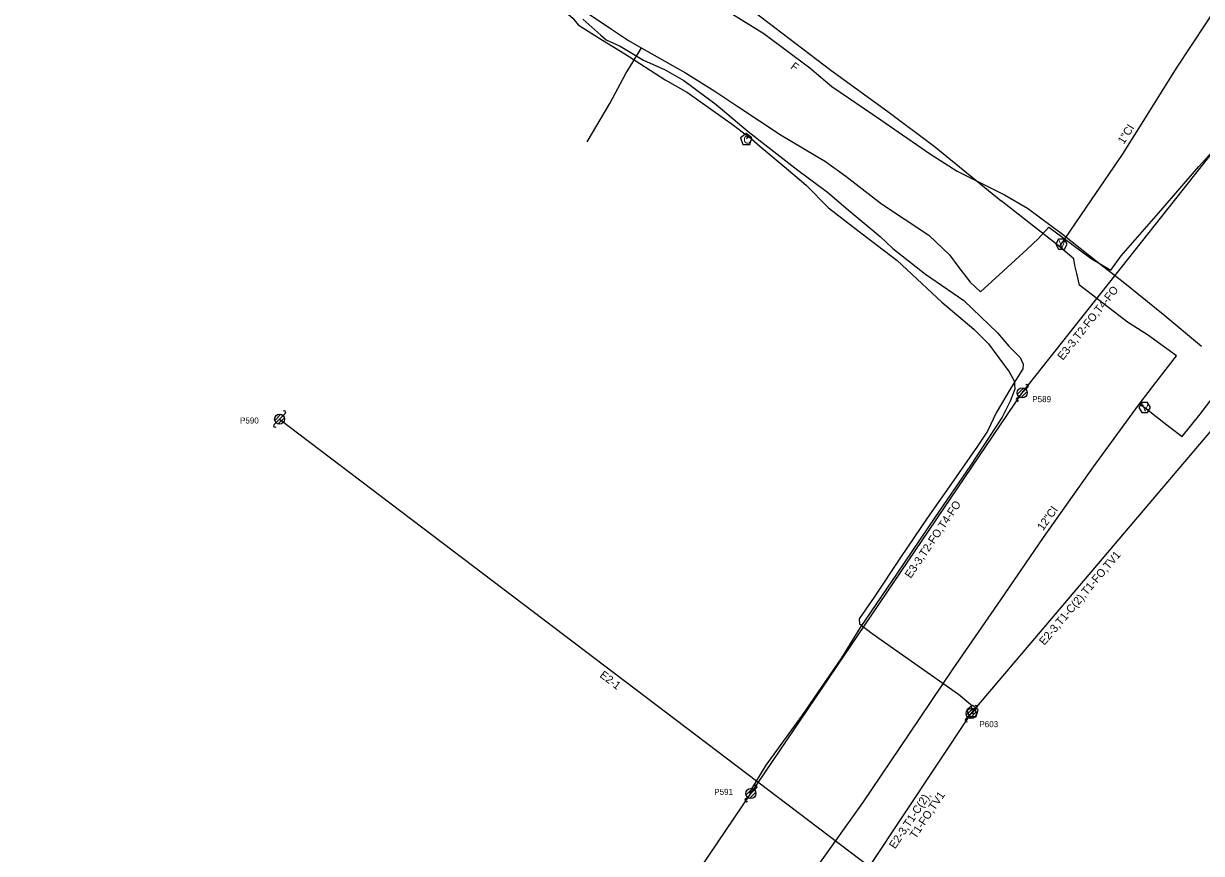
# Model space of a CAD drawing. Extents: x 1614474 to 1865144, y 1098877 to 1212550.
# Drawn here: x 1811697 to 1812286, y 1188970 to 1189385 of the extents above; entities that cross this region are included whole.
import ezdxf

# ---------------------------------------------------------------- set-up
doc = ezdxf.new("R2010")
doc.units = 0
for name, color, linetype in [('RD_EX_SU_Gas', 7, 'Continuous'), ('RD_EX_SU_H2O', 7, 'Continuous'), ('RD_EX_SU_Ovhd', 7, 'Continuous'), ('RD_EX_SU_Pole', 7, 'Continuous'), ('RD_EX_SU_Telecom', 7, 'Continuous'), ('RD_EX_SU_TX_H2O', 7, 'Continuous'), ('RD_EX_SU_TX_Pole', 7, 'Continuous'), ('RD_EX_SU_TX_Telecom', 7, 'Continuous')]:
    doc.layers.add(name, color=color, linetype=linetype)

# ---------------------------------------------------------------- blocks, each defined once
blk = doc.blocks.new('SUE_PP')
at = {"layer": 'RD_EX_SU_Pole'}
for p, q in [((-2.41, -0.65), (0.65, 2.41)), ((-1.77, -1.77), (1.77, 1.77)), ((-0.65, -2.41), (2.41, 0.65)), ((1.77, 1.77), (2.83, 2.83)), ((-2.83, -2.83), (-1.77, -1.77))]:
    blk.add_line(p, q, dxfattribs=at)
blk.add_circle((0, 0), 2.5, dxfattribs=at)
for centre, start, end in [((2.3, 3.36), 315, 135), ((-2.3, -3.36), 135, 315)]:
    blk.add_arc(centre, 0.75, start, end, dxfattribs=at)
blk = doc.blocks.new('SUE_WV')
at = {"layer": 'RD_EX_SU_H2O'}
blk.add_lwpolyline([(2.89, 0), (1.44, 2.5), (-1.44, 2.5), (-2.89, 0), (-1.44, -2.5), (1.44, -2.5)], close=True, dxfattribs=at)
blk.add_text('V', height=3.75, dxfattribs=at).set_placement((-1.43, -1.88))
blk = doc.blocks.new('SUE_TVP')
at = {"layer": 'RD_EX_SU_Telecom'}
blk.add_lwpolyline([(0, 3), (-2.85, 0.93), (-1.76, -2.43), (1.76, -2.43), (2.85, 0.93)], close=True, dxfattribs=at)
blk.add_text('C', height=4, dxfattribs=at).set_placement((-1.43, -2))
blk = doc.blocks.new('SUE_TPP')
at = {"layer": 'RD_EX_SU_Telecom'}
blk.add_lwpolyline([(0, 3), (-2.85, 0.93), (-1.76, -2.43), (1.76, -2.43), (2.85, 0.93)], close=True, dxfattribs=at)
blk.add_text('T', height=3.75, dxfattribs=at).set_placement((-1.25, -1.88))

msp = doc.modelspace()

# ---------------------------------------------------------------- linework, layer by layer
at = {"layer": 'RD_EX_SU_Gas'}
for points in [[(1811978.62, 1189391.11), (1811991.38, 1189382.56), (1811999.76, 1189376.95), (1812007.63, 1189372.44), (1812028.34, 1189360.8), (1812043.02, 1189351.63), (1812043, 1189351.62), (1812054.45, 1189343.92), (1812076.12, 1189329.64), (1812098.28, 1189316.44), (1812108.56, 1189309.04), (1812126.28, 1189295.18), (1812149.95, 1189279.57), (1812160.28, 1189269.79), (1812164.48, 1189264.02), (1812170.61, 1189256.05), (1812175.82, 1189251.33), (1812187.23, 1189261.59), (1812199.12, 1189272.51), (1812204.66, 1189277.83), (1812209.92, 1189283.55), (1812217.07, 1189278.4), (1812231.16, 1189267.99), (1812240.92, 1189262.02), (1812246.14, 1189269.26), (1812265.92, 1189291.95), (1812284.99, 1189313.9), (1812303.01, 1189333.69)], [(1811979.1, 1189326.23), (1811990.46, 1189345.51), (1811998.46, 1189360.42), (1812001.92, 1189366.05), (1812006.25, 1189373.23)]]:
    msp.add_lwpolyline(points, dxfattribs=at)
at = {"layer": 'RD_EX_SU_H2O'}
for points in [[(1811698.38, 1189649.37), (1811696.33, 1189642.69), (1811716.07, 1189631.57), (1811727.27, 1189624.19), (1811740.19, 1189614.8), (1811756.23, 1189601.68), (1811776.38, 1189587.41), (1811783.03, 1189583.6), (1811800.81, 1189574.54), (1811834.94, 1189557.09), (1811855.92, 1189546.76), (1811878.04, 1189532.45), (1811892.99, 1189521.5), (1811927.74, 1189491.64), (1811968.06, 1189460.58), (1811978.97, 1189453.42), (1811992.89, 1189443.78), (1812013.48, 1189429.12), (1812036.07, 1189412.42), (1812055.57, 1189396.84), (1812100.91, 1189362.09), (1812129.54, 1189341.4), (1812152.59, 1189324.09), (1812186.12, 1189296.74)], [(1812215.37, 1189273.71), (1812231.38, 1189297.27), (1812246.82, 1189320), (1812260.07, 1189340.98), (1812273.78, 1189363.08), (1812288.8, 1189385.82), (1812318.34, 1189431.67), (1812334.09, 1189455.86), (1812351.06, 1189482.68), (1812365.47, 1189504.6)], [(1812116.95, 1188995.65), (1812140.1, 1189030.08), (1812162.13, 1189062.69), (1812186.03, 1189097.22), (1812207.36, 1189128.42), (1812232.37, 1189163.69), (1812254.86, 1189194.52), (1812255.76, 1189195.96), (1812263.55, 1189205.99), (1812273.76, 1189219.21), (1812259.26, 1189229.8), (1812249.32, 1189236.06), (1812225.28, 1189254.55), (1812224.07, 1189260.46), (1812222.92, 1189264.39), (1812222.47, 1189267.8), (1812215.92, 1189273.24), (1812214.63, 1189274.34), (1812186.12, 1189296.74)], [(1812255.32, 1189195.25), (1812259.37, 1189192.44), (1812262.22, 1189190.08), (1812270.42, 1189183.54), (1812276.66, 1189178.9), (1812285.67, 1189190.08), (1812291.92, 1189198.39)], [(1811567.4, 1188231.07), (1811589.96, 1188265.01), (1811639.47, 1188338.74), (1811684.15, 1188405.74), (1811728.89, 1188473), (1811774.86, 1188540.59), (1811790.64, 1188564.19), (1811794.55, 1188569.69), (1811805.92, 1188562.31), (1811817.76, 1188554.55), (1811818.74, 1188553.96), (1811846.44, 1188595.11), (1811870.37, 1188629.14), (1811892.55, 1188662.25), (1811914.2, 1188695.96), (1811936.43, 1188730.7), (1811958.07, 1188762.91), (1811980.72, 1188796.49), (1812003.21, 1188830.12), (1812047.93, 1188896.23), (1812094.22, 1188963.78), (1812116.95, 1188995.65)]]:
    msp.add_lwpolyline(points, dxfattribs=at)
at = {"layer": 'RD_EX_SU_Ovhd'}
for p, q in [((1812196.69, 1189200.73), (1812309.05, 1189342.79)), ((1812061.04, 1189000.38), (1812196.69, 1189200.73)), ((1812171.15, 1189040.35), (1812308.36, 1189202.14)), ((1811825.38, 1189187.61), (1812120.25, 1188963.89)), ((1812120.25, 1188963.89), (1812171.15, 1189040.35)), ((1811919.87, 1188792.43), (1812061.04, 1189000.38))]:
    msp.add_line(p, q, dxfattribs=at)
at = {"layer": 'RD_EX_SU_Telecom'}
msp.add_line((1812171.36, 1189041.22), (1812172.02, 1189040.44), dxfattribs=at)
for points in [[(1811866.54, 1189460.89), (1811867.57, 1189462.27), (1811876.31, 1189455.22), (1811892.02, 1189444.39), (1811912.27, 1189431.03), (1811931.3, 1189417.22), (1811949.14, 1189403.92), (1811967.5, 1189391.86), (1811971.97, 1189388.13), (1811974.74, 1189384.76), (1811984.65, 1189378.44), (1811998.06, 1189370.34), (1812018.19, 1189357.33), (1812029.4, 1189350.87), (1812052.3, 1189334.6), (1812058.9, 1189329.54), (1812059.36, 1189328.63), (1812058.74, 1189327.92)], [(1812041.31, 1189396.63), (1812067.45, 1189380.42), (1812090.41, 1189363.34), (1812101.42, 1189353.94), (1812125.98, 1189337.24), (1812150.3, 1189320.5), (1812164.23, 1189311.53), (1812187.83, 1189299.74), (1812199.26, 1189293.17), (1812216.81, 1189280.11), (1812234.53, 1189266.09), (1812247.23, 1189256.27), (1812267.15, 1189240.03), (1812286.37, 1189224.13)], [(1811977.05, 1189387.58), (1811986.06, 1189379.62), (1811988.73, 1189377.2), (1811995.69, 1189374.13), (1812007.39, 1189367.1), (1812018.21, 1189362.25), (1812027.51, 1189356.89), (1812043.65, 1189344.91), (1812059.73, 1189331.44), (1812069.51, 1189323.69), (1812084.46, 1189312.15), (1812099.25, 1189301.13), (1812109.71, 1189292.19), (1812125.63, 1189278.91), (1812132.06, 1189272.87), (1812148.31, 1189260.14), (1812167.51, 1189246.91), (1812184.33, 1189230.77), (1812189.92, 1189224.1), (1812195.68, 1189218.44), (1812197.15, 1189215.13), (1812196.97, 1189212.67), (1812191.11, 1189203.4), (1812183.58, 1189190.7), (1812179.29, 1189181.61), (1812174.39, 1189174.02), (1812162.44, 1189157.11), (1812149.1, 1189138.06), (1812135.89, 1189118.37), (1812122.61, 1189098.55), (1812115.08, 1189087.68), (1812115.38, 1189085.22), (1812121.67, 1189080.44), (1812143.01, 1189065.32), (1812164.82, 1189050.06), (1812171.07, 1189044.83), (1812171.43, 1189041.93)], [(1812058.75, 1189327.94), (1812059.96, 1189328.86), (1812065.45, 1189324.08), (1812078.59, 1189313.02), (1812088.63, 1189304.63), (1812099.86, 1189293.32), (1812114.52, 1189281.84), (1812134.22, 1189266.96), (1812156.44, 1189246.02), (1812172.43, 1189232.65), (1812179.79, 1189225.24), (1812190.11, 1189211.3), (1812192.68, 1189206.79), (1812192.95, 1189202.5), (1812190.73, 1189196.56), (1812186.72, 1189188.51), (1812170.85, 1189164.4), (1812153.02, 1189138.33), (1812134.21, 1189110.64), (1812115.72, 1189083.45), (1812106.3, 1189068.24), (1812086.63, 1189039.55), (1812068.46, 1189014.56), (1812061.4, 1189002.77), (1812060.36, 1189000.35)]]:
    msp.add_lwpolyline(points, dxfattribs=at)

# ---------------------------------------------------------------- block references
at = {"layer": 'RD_EX_SU_H2O'}
for p in [(1812216.34, 1189275.12), (1812257.95, 1189193.42)]:
    msp.add_blockref('SUE_WV', p, dxfattribs=at)
at = {"layer": 'RD_EX_SU_Pole'}
for p in [(1812196.69, 1189200.73), (1811825.38, 1189187.61), (1812171.15, 1189040.35), (1812061.04, 1189000.38)]:
    msp.add_blockref('SUE_PP', p, dxfattribs=at)
at = {"layer": 'RD_EX_SU_Telecom'}
for name, p in [('SUE_TVP', (1812058.69, 1189327.38)), ('SUE_TPP', (1812171.88, 1189041.36))]:
    msp.add_blockref(name, p, dxfattribs=at)

# ---------------------------------------------------------------- texts
at = {"layer": 'RD_EX_SU_Ovhd'}
for s, rotation, p in [('E3-3,T2-FO,T4-FO', 51.65912, (1812217.02, 1189216.77)), ('E3-3,T2-FO,T4-FO', 55.90053, (1812140.94, 1189107.68)), ('E2-3,T1-C(2),T1-FO,TV1', 49.7014, (1812207.75, 1189074.23)), ('E2-1', 322.81176, (1811985.09, 1189058.91)), ('E2-3,T1-C(2),', 56.34739, (1812133.12, 1188972.4)), ('T1-FO,TV1', 56.34739, (1812143.42, 1188977.46))]:
    msp.add_text(s, height=4, rotation=rotation, dxfattribs=at).set_placement(p)
at = {"layer": 'RD_EX_SU_TX_H2O'}
for s, rotation, p in [('1"CI', 57.72236, (1812247.46, 1189324.76)), ('12"CI', 54.65971, (1812207.1, 1189131.52))]:
    msp.add_text(s, height=4, rotation=rotation, dxfattribs=at).set_placement(p)
at = {"layer": 'RD_EX_SU_TX_Pole'}
for s, p in [('P589', (1812201.71, 1189196.09)), ('P590', (1811805.61, 1189185.41)), ('P603', (1812175.26, 1189033.57)), ('P591', (1812042.7, 1188999.72))]:
    msp.add_text(s, height=3, dxfattribs=at).set_placement(p)
at = {"layer": 'RD_EX_SU_TX_Telecom'}
msp.add_text('F', height=4, rotation=323.37631, dxfattribs=at).set_placement((1812080.51, 1189363.23))

doc.saveas('drawing.dxf')
